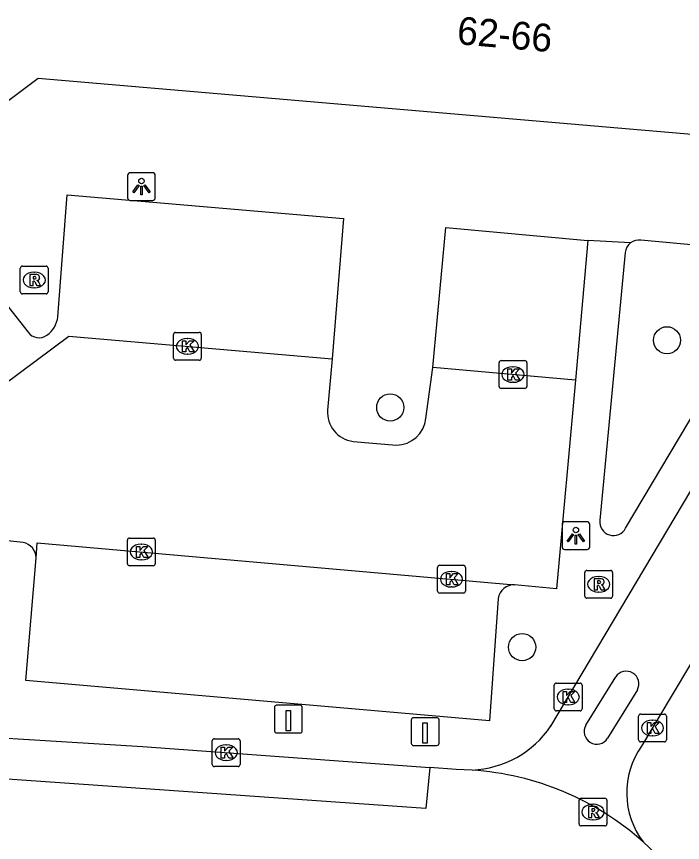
# Model space of a CAD drawing. Extents: x 159961 to 160856, y 382704 to 383353.
# Drawn here: x 160601.87 to 160625.85, y 382937.2 to 382966.93 of the extents above; entities that cross this region are included whole.
import ezdxf

# ---------------------------------------------------------------- set-up
doc = ezdxf.new("R2010")
doc.units = 0
for name, color, linetype in [('IMGEO_Boom', 7, 'Continuous'), ('IMGEO_Fietspad_open', 7, 'Continuous'), ('IMGEO_Kolk', 7, 'Continuous'), ('IMGEO_Laadpaal', 7, 'Continuous'), ('IMGEO_Lichtpunt', 7, 'Continuous'), ('IMGEO_Pand', 7, 'Continuous'), ('IMGEO_Pand_nummerreeks', 7, 'Continuous'), ('IMGEO_Rijbaan_lokaal_gesloten', 7, 'Continuous'), ('IMGEO_Rijbaan_lokaal_open', 7, 'Continuous'), ('IMGEO_Rioolput', 7, 'Continuous'), ('IMGEO_Voetpad_open', 7, 'Continuous')]:
    doc.layers.add(name, color=color, linetype=linetype)

msp = doc.modelspace()

# ---------------------------------------------------------------- linework, layer by layer
at = {"layer": 'IMGEO_Boom'}
for centre in [(160625.293, 382955.277), (160615.328, 382952.859), (160620.075, 382944.232)]:
    msp.add_circle(centre, 0.489, dxfattribs=at)
at = {"layer": 'IMGEO_Fietspad_open'}
for points in [[(160621.109, 382941.391), (160629.801, 382955.985)], [(160627.248, 382945.47), (160624.373, 382940.661)], [(160622.367, 382941.421), (160623.446, 382943.158)], [(160624.226, 382942.693), (160623.156, 382940.949)]]:
    msp.add_lwpolyline(points, dxfattribs=at)
for centre, radius, start, end in [((160623.826, 382942.909), 0.454, 331.6519, 146.7452), ((160622.769, 382941.198), 0.46, 150.957, 327.2651), ((160618.133, 382943.386), 3.582, 272.2842, 326.1679), ((160626.745, 382938.985), 2.905, 144.7488, 217.6099)]:
    msp.add_arc(centre, radius, start, end, dxfattribs=at)
at = {"layer": 'IMGEO_Kolk'}
for p, q in [((160607.524, 382954.635), (160607.524, 382955.487)), ((160607.599, 382955.561), (160608.451, 382955.561)), ((160608.525, 382955.487), (160608.525, 382954.635)), ((160608.012, 382955.341), (160608.037, 382955.341)), ((160608.451, 382954.561), (160607.599, 382954.561)), ((160608.035, 382954.781), (160608.01, 382954.781)), ((160619.321, 382954.544), (160620.173, 382954.544)), ((160619.246, 382953.618), (160619.246, 382954.47)), ((160619.734, 382954.324), (160619.759, 382954.324)), ((160620.247, 382954.47), (160620.247, 382953.618)), ((160619.757, 382953.764), (160619.732, 382953.764)), ((160620.173, 382953.544), (160619.321, 382953.544)), ((160605.866, 382947.232), (160605.866, 382948.084)), ((160605.941, 382948.158), (160606.793, 382948.158)), ((160606.867, 382948.084), (160606.867, 382947.232)), ((160606.354, 382947.938), (160606.379, 382947.938)), ((160606.377, 382947.378), (160606.352, 382947.378)), ((160606.793, 382947.158), (160605.941, 382947.158)), ((160617.033, 382946.25), (160617.033, 382947.102)), ((160617.108, 382947.176), (160617.96, 382947.176)), ((160618.034, 382947.102), (160618.034, 382946.25)), ((160617.521, 382946.956), (160617.546, 382946.956)), ((160617.96, 382946.176), (160617.108, 382946.176)), ((160617.544, 382946.396), (160617.519, 382946.396)), ((160621.309, 382942.937), (160622.161, 382942.937)), ((160621.234, 382942.011), (160621.234, 382942.863)), ((160621.722, 382942.717), (160621.747, 382942.717)), ((160622.235, 382942.863), (160622.235, 382942.011)), ((160621.745, 382942.157), (160621.72, 382942.157)), ((160622.161, 382941.937), (160621.309, 382941.937)), ((160624.27, 382940.894), (160624.27, 382941.746)), ((160624.345, 382941.82), (160625.197, 382941.82)), ((160625.271, 382941.746), (160625.271, 382940.894)), ((160624.758, 382941.6), (160624.783, 382941.6)), ((160608.921, 382940.007), (160608.921, 382940.859)), ((160608.996, 382940.933), (160609.848, 382940.933)), ((160609.922, 382940.859), (160609.922, 382940.007)), ((160625.197, 382940.82), (160624.345, 382940.82)), ((160624.781, 382941.04), (160624.756, 382941.04)), ((160609.409, 382940.713), (160609.434, 382940.713)), ((160609.848, 382939.933), (160608.996, 382939.933)), ((160609.432, 382940.153), (160609.407, 382940.153))]:
    msp.add_line(p, q, dxfattribs=at)
for points in [[(160607.524, 382954.635), (160607.524, 382955.487)], [(160607.599, 382955.561), (160608.451, 382955.561)], [(160608.525, 382955.487), (160608.525, 382954.635)], [(160607.845, 382955.261), (160607.968, 382955.261), (160607.968, 382955.11), (160608.098, 382955.261), (160608.262, 382955.261), (160608.116, 382955.11), (160608.269, 382954.861), (160608.117, 382954.861), (160608.032, 382955.025), (160607.968, 382954.958), (160607.968, 382954.861), (160607.845, 382954.861), (160607.845, 382955.261)], [(160608.451, 382954.561), (160607.599, 382954.561)], [(160619.321, 382954.544), (160620.173, 382954.544)], [(160619.246, 382953.618), (160619.246, 382954.47)], [(160619.567, 382954.244), (160619.69, 382954.244), (160619.69, 382954.093), (160619.82, 382954.244), (160619.984, 382954.244), (160619.838, 382954.093), (160619.991, 382953.844), (160619.839, 382953.844), (160619.754, 382954.008), (160619.69, 382953.941), (160619.69, 382953.844), (160619.567, 382953.844), (160619.567, 382954.244)], [(160620.247, 382954.47), (160620.247, 382953.618)], [(160620.173, 382953.544), (160619.321, 382953.544)], [(160605.866, 382947.232), (160605.866, 382948.084)], [(160605.941, 382948.158), (160606.793, 382948.158)], [(160606.867, 382948.084), (160606.867, 382947.232)], [(160606.187, 382947.858), (160606.31, 382947.858), (160606.31, 382947.707), (160606.44, 382947.858), (160606.604, 382947.858), (160606.458, 382947.707), (160606.611, 382947.458), (160606.459, 382947.458), (160606.374, 382947.622), (160606.31, 382947.555), (160606.31, 382947.458), (160606.187, 382947.458), (160606.187, 382947.858)], [(160606.793, 382947.158), (160605.941, 382947.158)], [(160617.033, 382946.25), (160617.033, 382947.102)], [(160617.108, 382947.176), (160617.96, 382947.176)], [(160618.034, 382947.102), (160618.034, 382946.25)], [(160617.354, 382946.876), (160617.477, 382946.876), (160617.477, 382946.725), (160617.607, 382946.876), (160617.771, 382946.876), (160617.625, 382946.725), (160617.778, 382946.476), (160617.626, 382946.476), (160617.541, 382946.64), (160617.477, 382946.573), (160617.477, 382946.476), (160617.354, 382946.476), (160617.354, 382946.876)], [(160617.96, 382946.176), (160617.108, 382946.176)], [(160621.309, 382942.937), (160622.161, 382942.937)], [(160621.234, 382942.011), (160621.234, 382942.863)], [(160621.555, 382942.637), (160621.678, 382942.637), (160621.678, 382942.486), (160621.808, 382942.637), (160621.972, 382942.637), (160621.826, 382942.486), (160621.979, 382942.237), (160621.827, 382942.237), (160621.742, 382942.401), (160621.678, 382942.334), (160621.678, 382942.237), (160621.555, 382942.237), (160621.555, 382942.637)], [(160622.235, 382942.863), (160622.235, 382942.011)], [(160622.161, 382941.937), (160621.309, 382941.937)], [(160624.27, 382940.894), (160624.27, 382941.746)], [(160624.345, 382941.82), (160625.197, 382941.82)], [(160625.271, 382941.746), (160625.271, 382940.894)], [(160624.591, 382941.52), (160624.714, 382941.52), (160624.714, 382941.369), (160624.844, 382941.52), (160625.008, 382941.52), (160624.862, 382941.369), (160625.015, 382941.12), (160624.863, 382941.12), (160624.778, 382941.284), (160624.714, 382941.217), (160624.714, 382941.12), (160624.591, 382941.12), (160624.591, 382941.52)], [(160608.921, 382940.007), (160608.921, 382940.859)], [(160608.996, 382940.933), (160609.848, 382940.933)], [(160609.922, 382940.859), (160609.922, 382940.007)], [(160625.197, 382940.82), (160624.345, 382940.82)], [(160609.242, 382940.633), (160609.365, 382940.633), (160609.365, 382940.482), (160609.495, 382940.633), (160609.659, 382940.633), (160609.513, 382940.482), (160609.666, 382940.233), (160609.514, 382940.233), (160609.429, 382940.397), (160609.365, 382940.33), (160609.365, 382940.233), (160609.242, 382940.233), (160609.242, 382940.633)], [(160609.848, 382939.933), (160608.996, 382939.933)]]:
    msp.add_lwpolyline(points, dxfattribs=at)
for centre, start, end in [((160607.601, 382955.485), 91.552, 178.448), ((160607.601, 382955.485), 91.552, 178.448), ((160608.449, 382955.485), 1.552, 88.448), ((160608.449, 382955.485), 1.552, 88.448), ((160607.601, 382954.637), 181.552, 268.448), ((160607.601, 382954.637), 181.552, 268.448), ((160608.449, 382954.637), 271.552, 358.448), ((160608.449, 382954.637), 271.552, 358.448), ((160619.323, 382954.468), 91.552, 178.448), ((160619.323, 382954.468), 91.552, 178.448), ((160620.171, 382954.468), 1.552, 88.448), ((160620.171, 382954.468), 1.552, 88.448), ((160619.323, 382953.62), 181.552, 268.448), ((160619.323, 382953.62), 181.552, 268.448), ((160620.171, 382953.62), 271.552, 358.448), ((160620.171, 382953.62), 271.552, 358.448), ((160605.943, 382948.082), 91.552, 178.448), ((160605.943, 382948.082), 91.552, 178.448), ((160606.791, 382948.082), 1.552, 88.448), ((160606.791, 382948.082), 1.552, 88.448), ((160605.943, 382947.234), 181.552, 268.448), ((160605.943, 382947.234), 181.552, 268.448), ((160606.791, 382947.234), 271.552, 358.448), ((160606.791, 382947.234), 271.552, 358.448), ((160617.11, 382947.1), 91.552, 178.448), ((160617.11, 382947.1), 91.552, 178.448), ((160617.958, 382947.1), 1.552, 88.448), ((160617.958, 382947.1), 1.552, 88.448), ((160617.11, 382946.252), 181.552, 268.448), ((160617.11, 382946.252), 181.552, 268.448), ((160617.958, 382946.252), 271.552, 358.448), ((160617.958, 382946.252), 271.552, 358.448), ((160621.311, 382942.861), 91.552, 178.448), ((160621.311, 382942.861), 91.552, 178.448), ((160622.159, 382942.861), 1.552, 88.448), ((160622.159, 382942.861), 1.552, 88.448), ((160621.311, 382942.013), 181.552, 268.448), ((160621.311, 382942.013), 181.552, 268.448), ((160622.159, 382942.013), 271.552, 358.448), ((160622.159, 382942.013), 271.552, 358.448), ((160624.347, 382941.744), 91.552, 178.448), ((160624.347, 382941.744), 91.552, 178.448), ((160625.195, 382941.744), 1.552, 88.448), ((160625.195, 382941.744), 1.552, 88.448), ((160608.998, 382940.857), 91.552, 178.448), ((160608.998, 382940.857), 91.552, 178.448), ((160609.846, 382940.857), 1.552, 88.448), ((160609.846, 382940.857), 1.552, 88.448), ((160624.347, 382940.896), 181.552, 268.448), ((160624.347, 382940.896), 181.552, 268.448), ((160625.195, 382940.896), 271.552, 358.448), ((160625.195, 382940.896), 271.552, 358.448), ((160608.998, 382940.009), 181.552, 268.448), ((160608.998, 382940.009), 181.552, 268.448), ((160609.846, 382940.009), 271.552, 358.448), ((160609.846, 382940.009), 271.552, 358.448)]:
    msp.add_arc(centre, 0.0765, start, end, dxfattribs=at)
for centre, major_axis, ratio, start_param, end_param in [((160608.011, 382955.061), (-0.387, 0.002), 0.722429, 4.712389, 7.853982), ((160608.036, 382955.061), (-0.39, 0.002), 0.717154, 1.570796, 4.712389), ((160619.733, 382954.044), (-0.387, 0.002), 0.722429, 4.712389, 7.853982), ((160619.758, 382954.044), (-0.39, 0.002), 0.717154, 1.570796, 4.712389), ((160606.353, 382947.658), (-0.387, 0.002), 0.722429, 4.712389, 7.853982), ((160606.378, 382947.658), (-0.39, 0.002), 0.717154, 1.570796, 4.712389), ((160617.52, 382946.676), (-0.387, 0.002), 0.722429, 4.712389, 7.853982), ((160617.545, 382946.676), (-0.39, 0.002), 0.717154, 1.570796, 4.712389), ((160621.721, 382942.437), (-0.387, 0.002), 0.722429, 4.712389, 7.853982), ((160621.746, 382942.437), (-0.39, 0.002), 0.717154, 1.570796, 4.712389), ((160624.757, 382941.32), (-0.387, 0.002), 0.722429, 4.712389, 7.853982), ((160624.782, 382941.32), (-0.39, 0.002), 0.717154, 1.570796, 4.712389), ((160609.408, 382940.433), (-0.387, 0.002), 0.722429, 4.712389, 7.853982), ((160609.433, 382940.433), (-0.39, 0.002), 0.717154, 1.570796, 4.712389)]:
    msp.add_ellipse(centre, major_axis=major_axis, ratio=ratio, start_param=start_param, end_param=end_param, dxfattribs=at)
at = {"layer": 'IMGEO_Laadpaal'}
for p, q in [((160611.16, 382942.057), (160611.16, 382941.216)), ((160611.16, 382942.057), (160611.16, 382941.216)), ((160612.076, 382942.141), (160611.235, 382942.141)), ((160612.076, 382942.141), (160611.235, 382942.141)), ((160612.16, 382941.225), (160612.16, 382942.066)), ((160612.16, 382941.225), (160612.16, 382942.066)), ((160616.085, 382941.604), (160616.085, 382940.763)), ((160616.085, 382941.604), (160616.085, 382940.763)), ((160617.001, 382941.688), (160616.16, 382941.688)), ((160617.001, 382941.688), (160616.16, 382941.688)), ((160617.085, 382940.772), (160617.085, 382941.613)), ((160617.085, 382940.772), (160617.085, 382941.613)), ((160611.244, 382941.141), (160612.085, 382941.141)), ((160611.244, 382941.141), (160612.085, 382941.141)), ((160616.169, 382940.688), (160617.01, 382940.688)), ((160616.169, 382940.688), (160617.01, 382940.688))]:
    msp.add_line(p, q, dxfattribs=at)
for points in [[(160611.575, 382941.954), (160611.735, 382941.954), (160611.735, 382941.221), (160611.575, 382941.221), (160611.575, 382941.954)], [(160616.5, 382941.501), (160616.66, 382941.501), (160616.66, 382940.768), (160616.5, 382940.768), (160616.5, 382941.501)]]:
    msp.add_lwpolyline(points, dxfattribs=at)
for centre, start, end in [((160611.238, 382942.063), 92.4484, 184.2845), ((160611.238, 382942.063), 92.4484, 184.2845), ((160612.082, 382942.063), 2.4484, 94.2845), ((160612.082, 382942.063), 2.4484, 94.2845), ((160616.163, 382941.61), 92.4484, 184.2845), ((160616.163, 382941.61), 92.4484, 184.2845), ((160617.007, 382941.61), 2.4484, 94.2845), ((160617.007, 382941.61), 2.4484, 94.2845), ((160611.238, 382941.219), 182.4484, 274.2845), ((160611.238, 382941.219), 182.4484, 274.2845), ((160612.082, 382941.219), 272.4484, 4.2845), ((160612.082, 382941.219), 272.4484, 4.2845), ((160616.163, 382940.766), 182.4484, 274.2845), ((160616.163, 382940.766), 182.4484, 274.2845), ((160617.007, 382940.766), 272.4484, 4.2845), ((160617.007, 382940.766), 272.4484, 4.2845)]:
    msp.add_arc(centre, 0.0779, start, end, dxfattribs=at)
at = {"layer": 'IMGEO_Lichtpunt'}
for p, q in [((160605.87, 382961.214), (160605.87, 382960.407)), ((160605.87, 382961.214), (160605.87, 382960.407)), ((160606.772, 382961.309), (160605.964, 382961.309)), ((160606.772, 382961.309), (160605.964, 382961.309)), ((160606.866, 382960.407), (160606.866, 382961.214)), ((160606.866, 382960.407), (160606.866, 382961.214)), ((160605.964, 382960.313), (160606.772, 382960.313)), ((160605.964, 382960.313), (160606.772, 382960.313)), ((160621.513, 382948.649), (160621.513, 382947.842)), ((160621.513, 382948.649), (160621.513, 382947.842)), ((160622.415, 382948.744), (160621.607, 382948.744)), ((160622.415, 382948.744), (160621.607, 382948.744)), ((160622.509, 382947.842), (160622.509, 382948.649)), ((160622.509, 382947.842), (160622.509, 382948.649)), ((160621.607, 382947.748), (160622.415, 382947.748)), ((160621.607, 382947.748), (160622.415, 382947.748))]:
    msp.add_line(p, q, dxfattribs=at)
for points in [[(160606.244, 382960.878), (160606.283, 382960.85), (160606.095, 382960.588), (160606.057, 382960.615), (160606.244, 382960.878)], [(160606.346, 382960.83), (160606.393, 382960.83), (160606.393, 382960.508), (160606.346, 382960.508), (160606.346, 382960.83)], [(160606.456, 382960.85), (160606.494, 382960.877), (160606.681, 382960.615), (160606.642, 382960.587), (160606.456, 382960.85)], [(160621.887, 382948.313), (160621.926, 382948.285), (160621.738, 382948.023), (160621.7, 382948.05), (160621.887, 382948.313)], [(160621.989, 382948.265), (160622.036, 382948.265), (160622.036, 382947.943), (160621.989, 382947.943), (160621.989, 382948.265)], [(160622.099, 382948.285), (160622.137, 382948.312), (160622.324, 382948.05), (160622.285, 382948.022), (160622.099, 382948.285)]]:
    msp.add_lwpolyline(points, dxfattribs=at)
for centre in [(160606.369, 382961.012), (160622.012, 382948.447)]:
    msp.add_circle(centre, 0.0994, dxfattribs=at)
for centre, start, end in [((160605.964, 382961.214), 90, 180), ((160605.964, 382961.214), 90, 180), ((160606.772, 382961.214), 0, 90), ((160606.772, 382961.214), 0, 90), ((160605.964, 382960.407), 180, 270), ((160605.964, 382960.407), 180, 270), ((160606.772, 382960.407), 270, 0), ((160606.772, 382960.407), 270, 360), ((160621.607, 382948.649), 90, 180), ((160621.607, 382948.649), 90, 180), ((160622.415, 382948.649), 0, 90), ((160622.415, 382948.649), 0, 90), ((160621.607, 382947.842), 180, 270), ((160621.607, 382947.842), 180, 270), ((160622.415, 382947.842), 270, 0), ((160622.415, 382947.842), 270, 360)]:
    msp.add_arc(centre, 0.0946, start, end, dxfattribs=at)
at = {"layer": 'IMGEO_Pand'}
msp.add_lwpolyline([(160637.67, 382961.705), (160602.645, 382964.701), (160588.123, 382953.831)], dxfattribs=at)
at = {"layer": 'IMGEO_Rijbaan_lokaal_gesloten'}
for points in [[(160600.944, 382940.986), (160606.405, 382940.651), (160616.753, 382939.899)], [(160616.753, 382939.899), (160616.611, 382938.423), (160585.624, 382940.588)]]:
    msp.add_lwpolyline(points, dxfattribs=at)
at = {"layer": 'IMGEO_Rijbaan_lokaal_open'}
for points in [[(160593.967, 382943.753), (160594.384, 382948.45), (160603.756, 382955.43), (160613.241, 382954.607)], [(160613.241, 382954.607), (160613.072, 382952.763)], [(160616.609, 382952.466), (160616.86, 382954.301)], [(160621.992, 382953.842), (160616.86, 382954.301)], [(160621.992, 382953.842), (160621.318, 382946.33), (160619.805, 382946.477)], [(160613.995, 382951.636), (160615.55, 382951.502)], [(160602.111, 382947.999), (160601.322, 382948.082)], [(160602.581, 382947.441), (160602.611, 382947.99), (160619.805, 382946.477)], [(160618.276, 382939.806), (160617.697, 382939.83), (160616.753, 382939.899)], [(160625.193, 382936.463), (160624.637, 382937.035), (160624.444, 382937.212)]]:
    msp.add_lwpolyline(points, dxfattribs=at)
for centre, radius, start, end in [((160614.121, 382952.681), 1.052, 175.5216, 263.1125), ((160615.539, 382952.578), 1.076, 270.5841, 354.0386), ((160601.989, 382947.419), 0.592, 2.1067, 78.1078), ((160617.554, 382929.459), 10.372, 48.373, 86.0078)]:
    msp.add_arc(centre, radius, start, end, dxfattribs=at)
at = {"layer": 'IMGEO_Rioolput'}
for p, q in [((160602.008, 382957.022), (160602.008, 382957.874)), ((160602.083, 382957.948), (160602.935, 382957.948)), ((160603.009, 382957.874), (160603.009, 382957.022)), ((160602.496, 382957.728), (160602.521, 382957.728)), ((160602.935, 382956.948), (160602.083, 382956.948)), ((160602.519, 382957.168), (160602.494, 382957.168)), ((160622.333, 382946.067), (160622.333, 382946.919)), ((160622.408, 382946.993), (160623.26, 382946.993)), ((160622.821, 382946.773), (160622.846, 382946.773)), ((160623.334, 382946.919), (160623.334, 382946.067)), ((160622.844, 382946.213), (160622.819, 382946.213)), ((160623.26, 382945.993), (160622.408, 382945.993)), ((160622.202, 382938.792), (160623.054, 382938.792)), ((160622.127, 382937.866), (160622.127, 382938.718)), ((160622.615, 382938.572), (160622.64, 382938.572)), ((160623.128, 382938.718), (160623.128, 382937.866)), ((160622.638, 382938.012), (160622.613, 382938.012)), ((160623.054, 382937.792), (160622.202, 382937.792))]:
    msp.add_line(p, q, dxfattribs=at)
for points in [[(160602.008, 382957.022), (160602.008, 382957.874)], [(160602.083, 382957.948), (160602.935, 382957.948)], [(160603.009, 382957.874), (160603.009, 382957.022)], [(160602.597, 382957.646), (160602.345, 382957.648), (160602.345, 382957.248)], [(160602.523, 382957.567), (160602.469, 382957.567), (160602.469, 382957.486)], [(160602.469, 382957.486), (160602.521, 382957.486)], [(160602.345, 382957.248), (160602.469, 382957.248), (160602.469, 382957.41), (160602.48, 382957.41)], [(160602.527, 382957.381), (160602.598, 382957.248), (160602.738, 382957.248), (160602.673, 382957.374)], [(160602.935, 382956.948), (160602.083, 382956.948)], [(160622.333, 382946.067), (160622.333, 382946.919)], [(160622.408, 382946.993), (160623.26, 382946.993)], [(160623.334, 382946.919), (160623.334, 382946.067)], [(160622.922, 382946.691), (160622.67, 382946.693), (160622.67, 382946.293)], [(160622.848, 382946.612), (160622.794, 382946.612), (160622.794, 382946.531)], [(160622.794, 382946.531), (160622.846, 382946.531)], [(160622.67, 382946.293), (160622.794, 382946.293), (160622.794, 382946.455), (160622.805, 382946.455)], [(160622.852, 382946.426), (160622.923, 382946.293), (160623.063, 382946.293), (160622.998, 382946.419)], [(160623.26, 382945.993), (160622.408, 382945.993)], [(160622.202, 382938.792), (160623.054, 382938.792)], [(160622.127, 382937.866), (160622.127, 382938.718)], [(160622.716, 382938.49), (160622.464, 382938.492), (160622.464, 382938.092)], [(160623.128, 382938.718), (160623.128, 382937.866)], [(160622.464, 382938.092), (160622.588, 382938.092), (160622.588, 382938.254), (160622.599, 382938.254)], [(160622.642, 382938.411), (160622.588, 382938.411), (160622.588, 382938.33)], [(160622.588, 382938.33), (160622.64, 382938.33)], [(160622.646, 382938.225), (160622.717, 382938.092), (160622.857, 382938.092), (160622.792, 382938.218)], [(160623.054, 382937.792), (160622.202, 382937.792)]]:
    msp.add_lwpolyline(points, dxfattribs=at)
for centre, radius, start, end in [((160602.085, 382957.872), 0.0765, 91.552, 178.448), ((160602.085, 382957.872), 0.0765, 91.552, 178.448), ((160602.933, 382957.872), 0.0765, 1.552, 88.448), ((160602.933, 382957.872), 0.0765, 1.552, 88.448), ((160602.505, 382957.675), 0.19, 274.7715, 282.9687), ((160602.529, 382957.471), 0.0964, 77.0061, 93.1865), ((160602.543, 382957.528), 0.0378, 276.6634, 79.6772), ((160602.596, 382957.536), 0.109, 350.3612, 89.416), ((160602.594, 382957.536), 0.112, 277.5842, 350.9817), ((160602.479, 382957.357), 0.0533, 26.0293, 88.6989), ((160602.578, 382957.321), 0.108, 29.5134, 73.7905), ((160602.085, 382957.024), 0.0765, 181.552, 268.448), ((160602.085, 382957.024), 0.0765, 181.552, 268.448), ((160602.933, 382957.024), 0.0765, 271.552, 358.448), ((160602.933, 382957.024), 0.0765, 271.552, 358.448), ((160622.41, 382946.917), 0.0765, 91.552, 178.448), ((160622.41, 382946.917), 0.0765, 91.552, 178.448), ((160623.258, 382946.917), 0.0765, 1.552, 88.448), ((160623.258, 382946.917), 0.0765, 1.552, 88.448), ((160622.83, 382946.72), 0.19, 274.7715, 282.9687), ((160622.854, 382946.516), 0.0964, 77.0061, 93.1865), ((160622.868, 382946.573), 0.0378, 276.6634, 79.6772), ((160622.921, 382946.581), 0.109, 350.3612, 89.416), ((160622.919, 382946.581), 0.112, 277.5842, 350.9817), ((160622.903, 382946.366), 0.108, 29.5134, 73.7905), ((160622.804, 382946.402), 0.0533, 26.0293, 88.6989), ((160622.41, 382946.069), 0.0765, 181.552, 268.448), ((160622.41, 382946.069), 0.0765, 181.552, 268.448), ((160623.258, 382946.069), 0.0765, 271.552, 358.448), ((160623.258, 382946.069), 0.0765, 271.552, 358.448), ((160622.204, 382938.716), 0.0765, 91.552, 178.448), ((160622.204, 382938.716), 0.0765, 91.552, 178.448), ((160623.052, 382938.716), 0.0765, 1.552, 88.448), ((160623.052, 382938.716), 0.0765, 1.552, 88.448), ((160622.715, 382938.38), 0.109, 350.3612, 89.416), ((160622.598, 382938.201), 0.0533, 26.0293, 88.6989), ((160622.624, 382938.519), 0.19, 274.7715, 282.9687), ((160622.648, 382938.315), 0.0964, 77.0061, 93.1865), ((160622.662, 382938.372), 0.0378, 276.6634, 79.6772), ((160622.713, 382938.38), 0.112, 277.5842, 350.9817), ((160622.697, 382938.165), 0.108, 29.5134, 73.7905), ((160622.204, 382937.868), 0.0765, 181.552, 268.448), ((160622.204, 382937.868), 0.0765, 181.552, 268.448), ((160623.052, 382937.868), 0.0765, 271.552, 358.448), ((160623.052, 382937.868), 0.0765, 271.552, 358.448)]:
    msp.add_arc(centre, radius, start, end, dxfattribs=at)
for centre, major_axis, ratio, start_param, end_param in [((160602.495, 382957.448), (-0.387, 0.002), 0.722429, 4.712389, 7.853982), ((160602.52, 382957.448), (-0.39, 0.002), 0.717154, 1.570796, 4.712389), ((160622.82, 382946.493), (-0.387, 0.002), 0.722429, 4.712389, 7.853982), ((160622.845, 382946.493), (-0.39, 0.002), 0.717154, 1.570796, 4.712389), ((160622.614, 382938.292), (-0.387, 0.002), 0.722429, 4.712389, 7.853982), ((160622.639, 382938.292), (-0.39, 0.002), 0.717154, 1.570796, 4.712389)]:
    msp.add_ellipse(centre, major_axis=major_axis, ratio=ratio, start_param=start_param, end_param=end_param, dxfattribs=at)
at = {"layer": 'IMGEO_Voetpad_open'}
for points in [[(160603.358, 382956.122), (160603.695, 382960.517), (160613.647, 382959.665), (160613.241, 382954.607)], [(160616.86, 382954.301), (160617.326, 382959.332), (160622.443, 382958.868)], [(160593.973, 382950.153), (160591.899, 382952.862), (160599.752, 382958.776), (160602.285, 382955.567)], [(160622.443, 382958.868), (160621.992, 382953.842)], [(160623.974, 382958.78), (160622.443, 382958.868)], [(160628.898, 382958.466), (160624.353, 382958.876)], [(160623.786, 382958.437), (160622.878, 382948.798)], [(160623.803, 382948.513), (160629.301, 382957.738)], [(160619.217, 382945.98), (160618.896, 382941.572), (160602.201, 382943.028), (160602.581, 382947.441)]]:
    msp.add_lwpolyline(points, dxfattribs=at)
for centre, radius, start, end in [((160624.272, 382958.394), 0.488, 127.6252, 174.9201), ((160624.275, 382958.386), 0.496, 81.0074, 127.4205), ((160602.423, 382956.223), 0.941, 305.3435, 353.8232), ((160602.682, 382955.855), 0.49, 215.9641, 305.5475), ((160623.366, 382948.738), 0.492, 172.956, 332.795), ((160619.792, 382945.896), 0.581, 88.7081, 171.7034)]:
    msp.add_arc(centre, radius, start, end, dxfattribs=at)

# ---------------------------------------------------------------- texts
at = {"layer": 'IMGEO_Pand_nummerreeks'}
msp.add_text('62-66', height=1, rotation=355.1109, dxfattribs=at).set_placement((160617.706, 382965.941))

doc.saveas('drawing.dxf')
